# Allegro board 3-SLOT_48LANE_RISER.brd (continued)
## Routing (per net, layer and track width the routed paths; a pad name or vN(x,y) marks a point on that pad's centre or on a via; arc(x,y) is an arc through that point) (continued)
85OHM_BOT_10INCH_DN: length 254
  BOTTOM w0.135: U43.1 -14.63,9.78 -14.63,12.53 -14.17,13.19 -13.48,13.31 -10.22,12.73 -9.99,12.89 -9.99,12.89 -9.88,12.97 -9.73,13.85 -9.99,14.22 -17.14,15.49 -17.32,15.74 -17.23,16.22 -17.01,16.37 -8.76,14.92 -8.4,15.16 -8.25,16.05 -8.49,16.4 -17.42,17.98 -17.54,18.14 -17.43,18.73 -17.26,18.86 -8.77,17.36 -8.39,17.63 -8.25,18.43 -8.54,18.85 -17.24,20.39 -17.38,20.58 -17.28,21.15 -17.1,21.27 -8.71,19.79 -8.29,20.09 -8.17,20.78 -8.42,21.29 -17.55,22.9 -17.71,23.13 -17.62,23.66 -17.45,23.77 -8.44,22.19 -8.04,22.46 -7.89,23.3 -8.15,23.67 -17.49,25.31 -17.64,25.51 -17.56,26.04 -17.37,26.2 -8.54,24.65 -8.12,24.94 -7.98,25.76 -8.23,26.12 -17.39,27.75 -17.52,27.94 -17.42,28.51 -17.26,28.63 -8.25,27.04 -7.87,27.3 -7.73,28.12 -8.01,28.52 -17.56,30.21 -17.67,30.38 -17.57,30.96 -17.39,31.09 -8.22,29.47 -7.82,29.75 -7.68,30.55 -7.97,30.96 -17.49,32.64 -17.6,32.79 -17.49,33.4 -17.32,33.52 -8.18,31.91 -7.79,32.18 -7.65,33 -7.93,33.39 -17.43,35.07 -17.58,35.28 -17.48,35.86 -17.33,35.96 -8.27,34.36 -7.79,34.69 -7.67,35.43 -7.96,35.84 -17.43,37.51 -17.55,37.69 -17.45,38.27 -17.26,38.39 -7.96,36.75 -7.53,37.05 -7.41,37.76 -7.75,38.25 -17.58,39.98 -17.71,40.17 -17.62,40.7 -17.39,40.86 -7.78,39.16 -7.36,39.46 -7.22,40.22 -7.52,40.65 -14.84,41.94 -14.95,42.09 -14.75,43.2 -14.75,45.47 U45.2
85OHM_BOT_10INCH_DP: length 254
  BOTTOM w0.135: U45.1 -15.06,45.46 -15.06,43.23 -15.27,42.02 -15.02,41.66 -7.7,40.37 -7.55,40.15 -7.64,39.63 -7.85,39.48 -17.46,41.18 -17.9,40.88 -18.03,40.1 -17.76,39.7 -7.93,37.97 -7.73,37.69 -7.81,37.23 -8.03,37.07 -17.33,38.71 -17.72,38.45 -17.88,37.62 -17.61,37.23 -8.13,35.56 -7.99,35.35 -8.07,34.87 -8.34,34.69 -17.4,36.28 -17.75,36.04 -17.9,35.21 -17.61,34.79 -8.1,33.12 -7.97,32.93 -8.07,32.36 -8.25,32.23 -17.39,33.84 -17.77,33.58 -17.92,32.72 -17.67,32.36 -8.15,30.68 -8.01,30.48 -8.1,29.93 -8.3,29.8 -17.46,31.41 -17.85,31.14 -18,30.3 -17.73,29.93 -8.18,28.25 -8.05,28.05 -8.15,27.48 -8.32,27.36 -17.33,28.95 -17.7,28.69 -17.72,28.57 -17.84,27.87 -17.56,27.48 -8.41,25.84 -8.3,25.69 -8.4,25.12 -8.61,24.97 -17.45,26.53 -17.85,26.21 -17.95,25.43 -17.67,25.03 -8.32,23.39 -8.21,23.23 -8.32,22.64 -8.51,22.51 -17.52,24.1 -17.9,23.84 -17.92,23.71 -18.03,23.05 -17.73,22.62 -8.63,21.02 -8.48,20.73 -8.57,20.26 -8.78,20.12 -17.17,21.6 -17.56,21.33 -17.7,20.51 -17.42,20.11 -8.72,18.57 -8.57,18.36 -8.67,17.8 -8.84,17.68 -17.33,19.18 -17.71,18.91 -17.86,18.07 -17.6,17.7 -8.67,16.12 -8.57,15.98 -8.68,15.34 -8.83,15.24 -17.08,16.7 -17.51,16.4 -17.64,15.67 -17.32,15.21 -10.17,13.95 -10.05,13.78 -10.16,13.14 -10.29,13.06 -13.48,13.62 -14.35,13.46 -14.94,12.62 -14.94,9.77 U43.2
85OHM_L2_5INCH_DN: length 127
  TOP w0.135: v2(-7.16,258.4) -7.39,258.17 -7.39,257.76 U29.2 ; v2(-7.16,278.38) -7.39,278.61 -7.39,279.02 U25.1
  IN2 w0.145: v2(-7.16,278.38) -7.4,278.14 -7.4,276.39 -6.9,275.67 -5.04,275.34 -4.69,274.85 -4.8,274.25 -5.3,273.9 -12.66,275.2 -12.82,275.08 -12.93,274.47 -12.81,274.31 -5.45,273.01 -5.1,272.51 -5.21,271.91 -5.71,271.56 -13.2,272.88 -13.37,272.77 -13.48,272.16 -13.36,271.99 -5.87,270.67 -5.52,270.17 -5.62,269.57 -6.12,269.22 -13.71,270.56 -13.88,270.45 -13.99,269.84 -13.87,269.67 -6.28,268.33 -5.93,267.83 -6.04,267.23 -6.53,266.89 -14.58,268.31 -14.75,268.19 -14.85,267.58 -14.74,267.41 -6.69,265.99 -6.34,265.5 -6.45,264.9 -6.95,264.55 -16.13,266.17 -16.44,265.95 -16.51,265.58 -16.29,265.28 -7.1,263.66 -6.75,263.16 -6.86,262.56 -7.36,262.21 -16.55,263.83 -16.85,263.62 -16.92,263.25 -16.7,262.94 -7.52,261.32 -7.17,260.82 -7.4,259.49 -7.4,258.64 v2(-7.16,258.4)
85OHM_L2_5INCH_DP: length 127
  TOP w0.135: U25.2 -7.69,279.02 -7.69,278.62 v2(-7.92,278.38) ; U29.1 -7.69,257.77 -7.69,258.17 v2(-7.92,258.4)
  IN2 w0.145: v2(-7.92,258.4) -7.68,258.64 -7.68,259.51 -7.46,260.75 -7.68,261.06 -16.87,262.68 -17.21,263.18 -17.11,263.78 -16.61,264.13 -7.42,262.51 -7.12,262.72 -7.05,263.09 -7.27,263.4 -16.45,265.02 -16.8,265.52 -16.7,266.12 -16.2,266.46 -7.01,264.84 -6.7,265.06 -6.64,265.43 -6.85,265.74 -14.9,267.16 -15.15,267.51 -15,268.35 -14.64,268.6 -6.6,267.18 -6.29,267.4 -6.23,267.77 -6.44,268.08 -14.03,269.41 -14.28,269.77 -14.13,270.61 -13.78,270.86 -6.19,269.52 -5.88,269.73 -5.81,270.11 -6.03,270.41 -13.53,271.74 -13.78,272.09 -13.63,272.93 -13.27,273.18 -5.77,271.86 -5.47,272.07 -5.4,272.44 -5.62,272.75 -12.98,274.05 -13.23,274.41 -13.08,275.24 -12.72,275.49 -5.36,274.2 -5.05,274.41 -4.99,274.78 -5.2,275.09 -7.04,275.41 -7.06,275.42 -7.68,276.3 -7.68,278.14 v2(-7.92,278.38)
85OHM_L2_10INCH_DN: length 254
  TOP w0.135: U37.2 -7.94,107.06 -7.94,106.66 v2(-8.18,106.43) ; v2(-8.18,72.01) -7.95,71.78 -7.95,71.37 U33.1
  IN2 w0.145: v2(-8.18,106.43) -7.94,106.18 -7.94,104.78 -7.79,103.98 -6.64,102.33 -6.77,101.6 -6.93,101.48 -12.68,102.49 -13.16,102.15 -13.27,101.53 -12.94,101.05 -4.14,99.5 -4.02,99.33 -4.13,98.72 -4.3,98.6 -13.09,100.15 -13.59,99.8 -13.7,99.21 -13.35,98.71 -4.56,97.16 -4.45,96.99 -4.55,96.38 -4.72,96.27 -13.51,97.82 -14,97.47 -14.11,96.87 -13.76,96.37 -4.86,94.8 -4.75,94.64 -4.85,94.03 -5.02,93.91 -13.92,95.48 -14.41,95.13 -14.52,94.53 -14.17,94.03 -5.17,92.45 -5.06,92.28 -5.16,91.67 -5.33,91.55 -14.33,93.14 -14.83,92.79 -14.93,92.19 -14.58,91.7 -4.58,89.93 -4.46,89.76 -4.57,89.16 -4.73,89.04 -14.74,90.8 -15.24,90.45 -15.34,89.86 -15,89.36 -4.97,87.59 -4.82,87.38 -4.92,86.81 -5.09,86.69 -15.15,88.46 -15.65,88.12 -15.76,87.52 -15.41,87.02 -5.29,85.24 -5.12,85 -5.22,84.45 -5.39,84.33 -15.57,86.13 -16.06,85.78 -16.17,85.18 -15.82,84.68 -5.6,82.88 -5.44,82.65 -5.53,82.17 -5.78,81.99 -15.98,83.79 -16.48,83.44 -16.58,82.84 -16.23,82.34 -5.8,80.51 -5.65,80.29 -5.75,79.74 -5.94,79.61 -16.39,81.45 -16.89,81.1 -16.99,80.5 -16.65,80.01 -6.44,78.21 -6.27,77.96 -6.35,77.52 -6.63,77.32 -16.8,79.11 -17.3,78.76 -17.41,78.17 -17.06,77.67 -7.69,76.02 -7.48,75.71 -7.94,73.12 -7.94,72.25 v2(-8.18,72.01)
85OHM_L2_10INCH_DP: length 254
  TOP w0.135: v2(-7.42,72.01) -7.65,71.78 -7.65,71.37 U33.2 ; U37.1 -7.64,107.06 -7.64,106.65 v2(-7.42,106.43)
  IN2 w0.145: v2(-7.42,106.43) -7.66,106.18 -7.66,104.81 -7.53,104.09 -6.34,102.39 -6.51,101.43 -6.87,101.18 -12.62,102.2 -12.91,101.99 -12.98,101.6 -12.77,101.3 -3.98,99.75 -3.79,99.49 -3.73,99.39 -3.88,98.56 -4.23,98.31 -13.03,99.86 -13.34,99.64 -13.4,99.27 -13.18,98.96 -4.4,97.42 -4.15,97.06 -4.3,96.22 -4.66,95.97 -13.44,97.52 -13.75,97.3 -13.81,96.93 -13.6,96.63 -4.7,95.06 -4.45,94.7 -4.6,93.86 -4.96,93.61 -13.85,95.18 -14.16,94.97 -14.23,94.6 -14.01,94.29 -5.01,92.7 -4.76,92.35 -4.91,91.51 -5.27,91.26 -14.26,92.84 -14.57,92.63 -14.64,92.26 -14.42,91.95 -4.42,90.19 -4.29,90 -4.16,89.82 -4.31,88.99 -4.67,88.74 -14.68,90.51 -14.98,90.29 -15.05,89.92 -14.83,89.61 -4.81,87.85 -4.53,87.45 -4.67,86.64 -5.03,86.39 -15.09,88.17 -15.4,87.95 -15.46,87.58 -15.25,87.28 -5.13,85.49 -4.83,85.06 -4.97,84.29 -5.32,84.04 -15.5,85.83 -15.81,85.62 -15.87,85.25 -15.66,84.94 -5.44,83.14 -5.15,82.72 -5.27,82 -5.71,81.69 -15.91,83.49 -16.22,83.28 -16.29,82.91 -16.07,82.6 -5.64,80.76 -5.36,80.36 -5.49,79.58 -5.88,79.31 -16.33,81.16 -16.63,80.94 -16.7,80.57 -16.48,80.26 -6.28,78.46 -5.97,78.03 -6.09,77.35 -6.56,77.02 -16.74,78.82 -17.05,78.6 -17.11,78.23 -16.9,77.92 -7.53,76.27 -7.18,75.78 -7.66,73.1 -7.66,72.44 -7.49,72.04 v2(-7.42,72.01)
85OHM_TOP_5INCH_DN: length 127
  TOP w0.135: U26.2 -14.93,340.62 -14.93,338.38 -15.14,337.17 -14.89,336.81 -7.57,335.52 -7.42,335.3 -7.51,334.78 -7.72,334.63 -17.34,336.33 -17.77,336.02 -17.91,335.24 -17.77,335.05 -17.63,334.85 -7.63,333.09 -7.4,332.76 -7.48,332.3 -7.66,332.18 -17.21,333.86 -17.6,333.6 -17.75,332.76 -17.48,332.38 -7.91,330.69 -7.7,330.39 -7.79,329.89 -7.93,329.79 -17.05,331.39 -17.43,331.13 -17.58,330.31 -17.29,329.91 -8.27,328.32 -8.09,328.05 -8.18,327.52 -8.33,327.41 -17.2,328.98 -17.59,328.71 -17.74,327.87 -17.47,327.5 -8.54,325.92 -8.44,325.77 -8.55,325.14 -8.7,325.04 -16.96,326.49 -17.38,326.2 -17.51,325.47 -17.19,325.01 -10.04,323.74 -9.92,323.57 -10.04,322.94 -10.16,322.85 -13.35,323.42 -14.22,323.26 -14.81,322.42 -14.81,319.58 U5.1
85OHM_TOP_5INCH_DP: length 127
  TOP w0.135: U5.2 -14.51,319.58 -14.51,322.33 -14.04,322.98 -13.35,323.11 -10.09,322.53 -9.86,322.69 -9.76,322.76 -9.6,323.65 -9.87,324.02 -17.01,325.28 -17.19,325.54 -17.1,326.02 -16.89,326.17 -8.63,324.72 -8.27,324.96 -8.12,325.85 -8.37,326.2 -17.3,327.78 -17.41,327.94 -17.31,328.53 -17.13,328.66 -8.26,327.09 -7.9,327.34 -7.77,328.13 -8.09,328.59 -17.12,330.19 -17.25,330.38 -17.2,330.66 -17.15,330.95 -16.98,331.07 -7.86,329.46 -7.69,329.59 -7.68,329.59 -7.51,329.71 -7.38,330.46 -7.56,330.72 -7.74,330.97 -17.31,332.66 -17.43,332.83 -17.37,333.13 -17.32,333.42 -17.14,333.54 -7.58,331.86 -7.2,332.12 -7.08,332.83 -7.45,333.36 -17.45,335.13 -17.59,335.32 -17.49,335.85 -17.27,336 -7.65,334.31 -7.23,334.61 -7.1,335.37 -7.39,335.79 -14.71,337.09 -14.82,337.24 -14.63,338.35 -14.63,340.62 U26.1
85OHM_TOP_10INCH_DN: length 254
  TOP w0.135: U34.2 -14.93,164.85 -14.93,162.61 -15.14,161.4 -14.89,161.04 -7.57,159.75 -7.42,159.53 -7.51,159.01 -7.72,158.86 -17.34,160.56 -17.77,160.26 -17.91,159.48 -17.63,159.08 -7.8,157.35 -7.6,157.07 -7.68,156.61 -7.9,156.45 -17.21,158.09 -17.6,157.83 -17.75,157 -17.48,156.61 -8.01,154.94 -7.86,154.73 -7.95,154.25 -8.21,154.07 -17.27,155.66 -17.63,155.42 -17.77,154.59 -17.48,154.17 -7.98,152.5 -7.84,152.31 -7.94,151.74 -8.12,151.61 -17.27,153.22 -17.64,152.96 -17.79,152.1 -17.54,151.74 -8.02,150.06 -7.88,149.86 -7.98,149.31 -8.17,149.18 -17.33,150.79 -17.72,150.52 -17.87,149.68 -17.61,149.31 -8.06,147.63 -7.92,147.43 -8.02,146.86 -8.2,146.74 -17.2,148.33 -17.57,148.07 -17.59,147.95 -17.71,147.25 -17.44,146.86 -8.28,145.22 -8.17,145.07 -8.27,144.5 -8.49,144.35 -17.32,145.91 -17.72,145.59 -17.83,144.81 -17.54,144.41 -8.2,142.77 -8.09,142.61 -8.19,142.02 -8.38,141.89 -17.39,143.48 -17.77,143.22 -17.79,143.09 -17.91,142.43 -17.6,142 -8.5,140.4 -8.36,140.11 -8.44,139.64 -8.65,139.5 -17.05,140.98 -17.43,140.71 -17.58,139.89 -17.29,139.49 -8.59,137.95 -8.44,137.74 -8.54,137.18 -8.71,137.06 -17.2,138.56 -17.59,138.29 -17.74,137.45 -17.47,137.08 -8.54,135.5 -8.44,135.36 -8.55,134.72 -8.7,134.62 -16.96,136.08 -17.38,135.78 -17.51,135.05 -17.19,134.59 -10.04,133.33 -9.92,133.16 -10.04,132.52 -10.16,132.44 -13.35,133 -14.22,132.84 -14.81,132 -14.81,129.16 U30.1
85OHM_TOP_10INCH_DP: length 254
  TOP w0.135: U30.2 -14.51,129.16 -14.51,131.91 -14.04,132.57 -13.35,132.69 -10.09,132.11 -9.86,132.27 -9.86,132.27 -9.76,132.35 -9.6,133.23 -9.87,133.6 -17.01,134.87 -17.19,135.12 -17.1,135.6 -16.89,135.75 -8.63,134.3 -8.27,134.54 -8.12,135.43 -8.37,135.78 -17.3,137.36 -17.41,137.52 -17.31,138.11 -17.13,138.24 -8.64,136.74 -8.26,137.01 -8.12,137.81 -8.42,138.23 -17.12,139.77 -17.25,139.96 -17.15,140.53 -16.98,140.65 -8.58,139.17 -8.16,139.47 -8.04,140.16 -8.29,140.67 -17.43,142.28 -17.58,142.51 -17.49,143.04 -17.32,143.15 -8.31,141.57 -7.91,141.84 -7.76,142.68 -8.02,143.05 -17.37,144.69 -17.51,144.89 -17.44,145.42 -17.24,145.58 -8.42,144.03 -7.99,144.32 -7.85,145.14 -8.11,145.5 -17.26,147.13 -17.39,147.32 -17.29,147.89 -17.13,148.01 -8.13,146.42 -7.75,146.68 -7.6,147.5 -7.88,147.9 -17.43,149.59 -17.55,149.76 -17.45,150.34 -17.26,150.47 -8.1,148.85 -7.7,149.13 -7.56,149.93 -7.84,150.34 -17.37,152.02 -17.47,152.17 -17.36,152.78 -17.19,152.9 -8.05,151.29 -7.66,151.56 -7.52,152.38 -7.8,152.77 -17.3,154.45 -17.45,154.66 -17.35,155.24 -17.2,155.34 -8.14,153.74 -7.67,154.07 -7.54,154.81 -7.83,155.22 -17.31,156.89 -17.43,157.07 -17.32,157.65 -17.14,157.77 -7.83,156.13 -7.41,156.43 -7.28,157.14 -7.62,157.63 -17.45,159.36 -17.59,159.55 -17.49,160.08 -17.27,160.24 -7.65,158.54 -7.23,158.84 -7.1,159.6 -7.39,160.03 -14.71,161.32 -14.82,161.47 -14.63,162.58 -14.63,164.85 U34.1
AT24C64_A0: length 4.7
  TOP w0.114: U7.1 315.16,41.63 315.65,42.11 315.65,43.61 R282.1 v2(315.16,44.78) R281.2
AT24C64_A1: length 4.7
  TOP w0.114: 313.89,41.12 313.89,41.88 314.34,42.32 314.34,43.64 R284.1 v2(313.89,44.78) R283.2
AT24C64_A2: length 4.7
  TOP w0.114: U7.3 312.62,41.78 313.13,42.29 313.13,43.58 R286.1 v2(312.62,44.78) R285.2
CLK_100M_CPU1_PE_FG_DN: length 76.6
  TOP w0.135: v2(280.62,9.91) 280.93,9.6 280.93,6.78 281.17,6.53 281.17,6.15 280.83,5.8 J5.A14 ; 301.31,56.32 U9.7 301.31,55.38 302.93,53.77 302.93,48.99 v2(303.15,48.77)
  IN2 w0.145: v2(280.62,9.91) 280.93,9.6 280.93,9.22 281.26,8.89 282.27,8.89 283.39,10.01 298.38,10.01 302.59,14.23 302.59,18.62 304.65,20.67 304.65,29.26 304.42,29.49 304.42,30.68 304.12,30.99 304.12,32.18 304.65,32.72 304.65,38.38 303.4,39.62 303.4,45.4 302.87,45.94 302.87,48.49 v2(303.15,48.77)
CLK_100M_CPU1_PE_FG_DP: length 76.6
  TOP w0.135: 300.91,56.32 U9.6 300.91,55.73 301.01,55.64 301.01,55.26 302.62,53.64 302.62,49.05 v2(302.34,48.77) ; v2(281.51,9.91) 281.23,9.63 281.23,6.91 281.48,6.66 281.48,6.15 281.83,5.8 J5.A13
  IN2 w0.145: v2(281.51,9.91) 281.21,9.6 281.21,9.34 281.37,9.17 282.16,9.17 283.27,10.29 298.26,10.29 298.76,10.79 298.76,10.95 299.2,11.39 299.36,11.39 300.72,12.75 300.72,12.91 301.17,13.36 301.33,13.36 302.32,14.34 302.32,18.73 304.37,20.79 304.37,21.59 304.28,21.68 304.28,22.45 304.37,22.54 304.37,23.44 304.24,23.57 304.24,24.2 304.37,24.32 304.37,24.9 304.24,25.03 304.24,25.66 304.37,25.79 304.37,26.36 304.24,26.49 304.24,27.12 304.37,27.25 304.37,29.14 304.14,29.37 304.14,30.57 303.84,30.87 303.84,32.3 304.37,32.83 304.37,34.3 304.26,34.41 304.26,35.04 304.37,35.15 304.37,36.01 304.26,36.12 304.26,36.75 304.37,36.87 304.37,38.26 303.13,39.51 303.13,45.29 302.59,45.82 302.59,46.96 302.46,47.09 302.46,47.72 302.59,47.84 302.59,48.51 v2(302.34,48.77)
CLK_100M_PEX8796_DN: length 3.8
  TOP w0.135: 301.31,61.07 U9.24 301.31,61.59 301.36,61.64 301.36,62.39 301.95,62.98 301.95,64.12 R127.1
CLK_100M_PEX8796_DP: length 3.8
  TOP w0.135: 301.71,61.07 U9.23 301.71,61.58 301.66,61.63 301.66,62.26 302.26,62.86 302.26,64.17 R126.1
CLK_100M_PEX8796_R_DN: length 302.9
  TOP w0.135: v2(276.2,30.3) 275.95,30.56 275.95,33.81 276.96,34.82 276.96,38.13 277.95,39.12 277.95,45.21 278.78,46.04 278.88,46.04 278.88,46.03 278.98,46.03 279.29,46.35 279.29,46.45 279.29,46.45 279.29,46.55 281.17,48.43 281.34,48.43 281.76,48.86 281.76,49.02 283.57,50.83 283.77,50.83 284.08,51.14 284.08,51.34 291.79,59.05 291.89,59.05 291.89,59.05 291.99,59.05 292.3,59.36 292.3,59.46 292.3,59.46 292.3,59.56 294.31,61.57 294.54,61.57 294.73,61.76 294.73,61.99 294.93,62.19 295.16,62.19 295.35,62.38 295.35,62.61 295.55,62.81 295.78,62.81 295.98,63.01 295.98,63.23 297.18,64.44 v6(297.18,65.76) 297.18,67.49 297.95,68.26 301.39,68.26 301.93,67.72 301.93,65.66 R127.2
  IN2 w0.145: v3(56.85,67.16) 56.85,67.28 56.71,67.42 56.49,67.42 56.24,67.17 56.24,61.84 65.51,52.58 73.27,52.58 74.62,51.23 74.76,51.23 75.24,50.75 75.24,50.61 76.37,49.48 81.33,49.48 81.46,49.61 82.09,49.61 82.21,49.48 82.79,49.48 82.91,49.61 83.54,49.61 83.67,49.48 93.48,49.48 101.41,57.41 154.68,57.41 181.15,30.94 258.64,30.94 258.77,31.06 259.4,31.06 259.53,30.94 260.11,30.94 260.23,31.06 260.86,31.06 260.99,30.94 273.08,30.94 273.99,31.85 275.4,31.85 275.92,31.33 275.92,30.58 v2(276.2,30.3)
  BOTTOM w0.135: U1.W2 57.25,67.56 v3(56.85,67.16)
CLK_100M_PEX8796_R_DP: length 303
  TOP w0.135: R126.2 302.23,65.66 302.23,67.85 301.51,68.57 297.83,68.57 296.88,67.62 v6(296.88,67.34) 296.88,64.57 277.65,45.34 277.65,39.24 276.66,38.25 276.66,34.95 275.64,33.93 275.64,30.56 v2(275.39,30.3)
  IN2 w0.145: v3(56.85,67.96) 56.85,67.82 56.73,67.7 56.38,67.7 55.96,67.29 55.96,61.73 65.39,52.3 73.15,52.3 76.25,49.2 93.6,49.2 101.52,57.13 154.57,57.13 181.04,30.66 273.19,30.66 274.11,31.57 275.29,31.57 275.64,31.22 275.64,30.56 v2(275.39,30.3)
  BOTTOM w0.135: U1.W3 57.25,68.36 v3(56.85,67.96)
CLK_100M_SLOT1_DN: length 3.8
  TOP w0.135: 303.09,58.5 U9.15 303.61,58.5 303.65,58.45 304.49,58.45 305.08,57.86 306.13,57.86 R340.1
CLK_100M_SLOT1_DP: length 3.8
  TOP w0.135: 303.09,58.1 U9.14 303.6,58.1 303.65,58.15 304.36,58.15 304.96,57.55 306.18,57.55 R143.1
CLK_100M_SLOT1_R_DN: length 79
  TOP w0.135: v2(309.2,51.21) 308.97,51.43 308.97,57.28 308.37,57.88 307.67,57.88 R340.2
  IN2 w0.145: v2(309.2,51.21) 308.94,50.95 308.94,50.22 308.33,49.61 306.45,49.61 305.89,50.16 301.72,50.16 301.04,49.49 301.04,46.3 301.96,45.39 301.96,42.02 301.7,41.77 301.7,40.17 301.96,39.92 301.96,35.99 301.27,35.31 301.27,32.74 302.03,31.98 302.03,19.97 301.43,19.37 301.43,15.08 297.15,10.79 282.51,10.79 281.74,11.57 281.74,13.49 281.69,13.54 281.39,13.74 281.2,13.68 J1.A14
CLK_100M_SLOT1_R_DP: length 79
  TOP w0.135: R143.2 307.67,57.58 308.24,57.58 308.66,57.16 308.66,55.75 308.54,55.62 308.54,54.73 308.66,54.6 308.66,51.49 v2(308.38,51.21)
  IN2 w0.145: v2(308.38,51.21) 308.66,50.93 308.66,50.33 308.22,49.89 306.57,49.89 306.01,50.44 304.6,50.44 304.48,50.56 303.85,50.56 303.74,50.44 303.14,50.44 303.02,50.56 302.39,50.56 302.28,50.44 301.6,50.44 300.76,49.61 300.76,48.25 300.65,48.13 300.65,47.5 300.76,47.39 300.76,46.19 301.68,45.27 301.68,44.18 301.56,44.07 301.56,43.44 301.68,43.33 301.68,42.14 301.42,41.88 301.42,40.06 301.68,39.8 301.68,37.73 301.58,37.63 301.58,36.94 301.68,36.84 301.68,36.11 300.99,35.42 300.99,32.62 301.75,31.86 301.75,26.66 301.63,26.53 301.63,25.85 301.75,25.72 301.75,25.14 301.63,25.02 301.63,24.34 301.75,24.21 301.75,23.1 301.64,22.98 301.64,22.36 301.75,22.24 301.75,21.39 301.64,21.27 301.64,20.64 301.75,20.53 301.75,20.09 301.15,19.49 301.15,15.2 300.16,14.2 299.99,14.2 299.55,13.76 299.55,13.6 297.03,11.07 282.63,11.07 282.02,11.68 282.02,13.61 281.74,13.88 281.52,13.99 281.52,14 281.46,14.19 J1.A13
CLK_100M_SLOT2_DN: length 4
  TOP w0.135: 303.09,59.7 U9.18 303.55,59.7 303.6,59.65 304.06,59.65 304.47,60.07 305.06,60.07 305.67,60.68 306.16,60.68 R125.1
CLK_100M_SLOT2_DP: length 4
  TOP w0.135: 303.09,59.3 U9.17 303.58,59.3 303.63,59.35 304.18,59.35 304.6,59.76 305.19,59.76 305.79,60.37 306.16,60.37 R124.1
CLK_100M_SLOT2_R_DN: length 62.2
  TOP w0.135: R125.2 307.67,60.68 308.74,60.68 310.77,58.65 310.77,54.1 v2(311,53.87)
  BOTTOM w0.135: v2(311,53.87) 310.8,53.67 310.8,35.51 309.55,34.26 299.7,34.26 296.42,30.99 283.03,30.99 281.64,32.39 281.64,33.86 281.51,33.99 281.38,34.06 281.2,34 J2.A14
CLK_100M_SLOT2_R_DP: length 62.1
  TOP w0.135: v2(310.19,53.87) 310.47,54.15 310.47,58.53 308.62,60.37 307.67,60.37 R124.2
  BOTTOM w0.135: v2(310.19,53.87) 310.49,53.57 310.49,49.43 310.29,49.23 310.29,48.79 310.49,48.59 310.49,35.64 309.43,34.57 301.84,34.57 301.69,34.72 301.2,34.72 301.04,34.57 299.57,34.57 298.61,33.61 298.51,33.61 298.41,33.61 298.09,33.3 298.09,33.2 298.09,33.09 296.29,31.29 295.42,31.29 295.24,31.47 294.8,31.47 294.62,31.29 290.45,31.29 290.27,31.47 289.83,31.47 289.65,31.29 285.95,31.29 285.77,31.47 285.33,31.47 285.15,31.29 283.16,31.29 282.73,31.73 282.73,31.94 282.44,32.23 282.23,32.23 281.94,32.51 281.94,33.99 281.69,34.25 281.52,34.33 281.46,34.51 J2.A13
CLK_100M_SLOT3_DN: length 4
  TOP w0.135: R123.1 299.13,64.14 299.13,63.08 300.16,62.06 300.16,61.58 300.11,61.54 U9.27 300.11,61.07
CLK_100M_SLOT3_DP: length 4
  TOP w0.135: 300.51,61.07 U9.26 300.51,61.57 300.46,61.61 300.46,62.18 299.44,63.21 299.44,64.14 R122.1
CLK_100M_SLOT3_R_DN: length 27.4
  TOP w0.135: R123.2 299.13,65.66 299.13,66.58 v2(298.86,66.85)
  BOTTOM w0.135: v2(298.86,66.85) 299.09,67.08 299.09,67.41 298.81,67.69 297.18,67.69 296.65,67.16 293.29,67.16 293.12,66.98 292.68,66.98 292.5,67.16 289.44,67.16 289.26,66.98 288.82,66.98 288.64,67.16 284.71,67.16 282.64,69.23 282.64,72.02 281.64,73.02 281.64,74.5 281.51,74.63 281.38,74.7 281.2,74.64 J3.A14
CLK_100M_SLOT3_R_DP: length 27.5
  TOP w0.135: R122.2 299.44,65.66 299.44,66.62 v2(299.67,66.86)
  BOTTOM w0.135: J3.A13 281.46,75.15 281.52,74.97 281.69,74.89 281.94,74.63 281.94,73.15 282.95,72.14 282.95,69.35 284.84,67.46 296.52,67.46 297.06,68 298.93,68 299.39,67.54 299.39,67.14 v2(299.67,66.86)
CLK_BUF_CKPWRGD: length 6.8
  TOP w0.114: Q4.D 299.8,51.02 R4.2 299.31,55.26 299.71,55.66 U9.3 299.71,56.32
CLK_BUF_HIBW_BYPM_LOBW_N: length 4
  TOP w0.178: 299.31,56.32 U9.2 299.31,55.67 298.79,55.14 298.79,54.94
  TOP w0.254: R1.2 R2.1 298.79,53.94 298.79,54.94
CPLD_PWRBRK_BUF_N: length 75.9
  TOP w0.114: v2(286.67,58.17) 286.7,58.13 R310.1 285.39,57.4 U8.4 ; U47.2 276.68,29.31 277.47,30.1 277.47,31.29 278.46,32.28 279.55,32.28 279.86,32.59 279.86,34.09 280.7,34.92 280.7,36.32 281.08,36.7 281.94,36.7 284.74,39.5 v2(284.74,41.1) ; U19.2 v2(283.54,85.72) ; v2(283.54,45.34) 283.41,45.21 U20.2
  IN2 w0.147: v2(284.74,41.1) 284.71,41.1 283.05,42.76 283.05,44.84 v2(283.54,45.34) 283.54,47.02 287.17,50.65 287.17,56.92 286.67,57.43 v2(286.67,58.17) 285.73,58.17 285.1,58.79 285.1,61.81 280.9,66.01 280.9,69.34 286.84,75.29 286.84,78.77 282.88,82.73 282.88,85.52 283.08,85.72 v2(283.54,85.72)
CPLD_PWRBRK_N: length 80.8
  TOP w0.114: U8.2 283.54,58.17 283.8,57.91 283.8,56.41 R309.2 283.78,55.9 284.05,55.63 286.08,55.63 v2(286.59,56.13)
  IN2 w0.147: v2(266.4,25.02) 267.92,26.54 276.28,26.54 278.36,28.63 281.04,28.63 284.01,31.6 286.31,31.6 287.73,33.02 287.73,34.19 286.69,35.23 286.69,38.23 282.53,42.39 282.53,46.74 286.59,50.8 v2(286.59,56.13)
  BOTTOM w0.114: J5.B30 264.83,5.58 263.7,6.71 263.7,11.86 263.98,12.14 263.98,13.79 264.72,14.53 264.72,17.86 265.86,19 265.86,20.27 266.52,20.93 266.52,24.89 v2(266.4,25.02)
CPLD_SLOT1_PWRBRK_N: length 3.7
  TOP w0.114: R40.1 274.76,25.15 R39.1 R164.2 v2(275.92,25.91) 276.03,26.02 U47.4
CPLD_SLOT1_PWRBRK_R1_N: length 10.8
  TOP w0.114: J1.B12 282.83,20.83 279.96,23.7 275.7,23.7 R39.2
CPLD_SLOT1_PWRBRK_R2_N: length 11.6
  TOP w0.114: J1.B30 266.96,21.56 270.96,21.56 272.35,22.95 272.35,24.62 272.87,25.15 R40.2
CPLD_SLOT2_PWRBRK_N: length 4.1
  TOP w0.114: R221.1 R216.1 R154.2 285.14,43.45 285.35,43.66 v2(285.35,44.07) 285.35,44.37 285.16,44.56 U20.4
CPLD_SLOT2_PWRBRK_R1_N: length 3.3
  TOP w0.114: J2.B12 283.8,40.72 R216.2
CPLD_SLOT2_PWRBRK_R2_N: length 19.2
  TOP w0.114: R221.2 v2(278.74,42.65)
  IN1 w0.147: v2(278.74,42.65) 267.73,42.65 J2.B30
CPLD_SLOT3_PWRBRK_N: length 3.8
  TOP w0.114: U19.4 284.03,85.08 283.8,84.84 v2(283.8,84.71) R214.1 ; R155.2 R214.1 ; R214.1 R215.1
CPLD_SLOT3_PWRBRK_R1_N: length 3.2
  TOP w0.114: R214.2 283.8,81.36 J3.B12
CPLD_SLOT3_PWRBRK_R2_N: length 19.1
  TOP w0.114: J3.B30 267.6,83.17 R215.2
DC_PEX8747_AA18: length 0.6
  BOTTOM w0.114: U1.AA18 v3(55.25,80.77)
DC_PEX8747_AA21: length 0.6
  BOTTOM w0.114: U1.AA21 v3(56.05,83.17)
DC_PEX8747_B9: length 0.6
  BOTTOM w0.114: U1.B9 v3(70.45,72.76)
DC_PEX8747_F13: length 0.6
  BOTTOM w0.114: U1.F13 v3(68.05,76.77)
DC_PEX8747_F20: length 0.6
  BOTTOM w0.114: U1.F20 v3(68.05,82.37)
DC_PEX8747_F21: length 0.6
  BOTTOM w0.114: U1.F21 67.65,82.77 v3(67.25,83.17)
DC_PEX8747_N22: length 0.6
  BOTTOM w0.114: U1.N22 62.05,83.57 v3(61.65,83.97)
DC_PEX8747_Y16: length 0.6
  BOTTOM w0.114: U1.Y16 v3(56.05,79.17)
DC_PEX8747_Y20: length 0.6
  BOTTOM w0.114: U1.Y20 v3(56.05,82.37)
EMC1413_ADDR: length 4.9
  TOP w0.114: U10.7 184.33,78 v2(185.98,76.35) 186.49,75.84 187.61,75.84 R150.2
EMC1413_ALERT_N: length 4.6
  TOP w0.114: U10.8 184.83,78.5 v2(185.35,77.98) 186.14,77.19 187.41,77.19 R151.2
I2C_ADDR0: length 7.7
  TOP w0.102: v3(68.05,69.56) 67.67,69.18 67.13,69.18 66.87,68.92 66.87,68.59 66.5,68.22 66.5,65.66
  TOP w0.114: R94.2 R108.1 66.37,64.96 66.5,65.09 66.5,65.66
  BOTTOM w0.114: U1.F5 v3(68.05,69.56)
I2C_MUX_ADD_A0: length 6.7
  TOP w0.114: U2.1 308.04,41.16 308.54,41.66 v2(309.32,41.66) 309.45,41.78 309.45,43.69 309.72,43.96 R84.1 R83.2
I2C_MUX_ADD_A1: length 5.9
  TOP w0.114: R81.2 v2(308.81,44.73) R82.1 308.23,43.38 308.23,41.88 307.39,41.04 U2.2
I2C_MUX_ADD_A2: length 5.7
  TOP w0.114: R79.2 R80.1 306.45,31.07 306.45,31.85 v2(306.2,32.11) 306.09,32.21 U2.21
I2C_MUX_RST_N: length 3.4
  TOP w0.114: R78.2 307.67,42.62 v2(307.37,42.32) 307.34,42.32 306.74,41.72 U2.3
I2C_PCA9548_SC1_SLOT3_R_SCL: length 3.2
  TOP w0.114: U2.7 304.14,41.53 v2(304.1,41.57) 303.61,42.06 R22.1
I2C_PCA9548_SC1_SLOT3_SCL: length 36.4
  TOP w0.114: R22.2 304.24,44.6 v2(304.24,44.7) R98.2 ; v2(292.22,65.11) Q15.D 291.78,67.24 R226.1
  BOTTOM w0.114: v2(304.24,44.7) 302.49,44.7 300.2,46.99 294.57,46.99 292.1,49.45 292.1,62.63 291.97,62.77 291.75,62.77 291.62,62.9 291.62,63.09 291.75,63.22 291.97,63.22 292.1,63.36 292.1,64.99 v2(292.22,65.11)
I2C_PCA9548_SC3_SLOT2_R_SCL: length 4.6
  TOP w0.114: R26.1 299.67,41.68 v2(299.82,41.53) 300.05,41.3 301.25,41.3 301.54,41.01 U2.11
I2C_PCA9548_SC3_SLOT2_SCL: length 27
  TOP w0.114: v2(295.56,26.26) 295.56,26.43 295.55,26.43 295.55,26.65 295.23,26.98 R228.1 294.69,27.16 294.32,26.8 Q21.D ; R102.2 298.4,44.68 v2(298.4,44.32) 298.76,43.96 R26.2
  IN2 w0.147: v2(295.56,26.26) 295.56,26.87 297.52,28.83 297.52,41.47 297,41.99 297,43.26 298.07,44.32 v2(298.4,44.32)
I2C_PCA9548_SC4_SLOT1_R_SCL: length 5.8
  TOP w0.114: U2.14 301.54,33.72 299.8,31.98 299.8,30.58 v2(299.54,30.33) R339.1
I2C_PCA9548_SC4_SLOT1_SCL: length 12.9
  TOP w0.114: R339.2 299.54,28.52 v2(299.19,28.17) 299.54,27.81 R145.2 ; R307.1 296.6,23.11 Q20.D v2(299.88,22.1)
  IN2 w0.147: v2(299.19,28.17) 299.09,28.07 299.09,22.89 v2(299.88,22.1)
I2C_PCA9548_SC5_3V3_PE_SCL: length 177.4
  TOP w0.114: CON1.2 191.13,113.78 192.43,112.47 192.43,107.75 188.16,103.48 138.18,103.48 134.42,107.24 118.24,107.24 109.04,98.04 109.04,65 127.65,46.39 127.65,41.61 127.26,41.22 127.26,37.14 Q25.S 124.99,35.62 124.79,35.81 v2(124.79,36.58) 123.09,36.58 122.86,36.34 R194.2 R234.2 122.13,37.69 120.68,37.69 120.34,37.36 U12.7
I2C_PCA9548_SC5_P1V8_SCL: length 69.5
  TOP w0.114: v3(68.05,71.16) 68.47,70.75 70.86,70.75 71.38,70.23 71.38,69.95 71.88,69.44 73.53,69.44 74.07,69.98 93.28,69.98 v7(120.42,42.84) 120.34,42.76 U12.2
  BOTTOM w0.114: U1.F7 v3(68.05,71.16) ; R277.2 120.42,41.37 v7(120.42,42.84)
I2C_PCA9548_SC5_PE_R_SCL: length 3.6
  TOP w0.114: R28.1 301.83,32.77 v2(302.08,33.02) 302.84,33.78 U2.16
I2C_PCA9548_SC5_PE_SCL: length 199.1
  TOP w0.114: R234.1 122.99,38.12 v2(123.52,37.59) 124.56,37.59 Q25.D ; R28.2 301.83,30.56 v2(301.17,29.89) R104.2
  IN2 w0.147: v2(280.39,24.1) 280.39,23.11 279.25,21.97 267.93,21.97 266.57,23.32 257.74,23.32 254.74,26.31 180.69,26.31 162.94,44.07 130.35,44.07 123.88,37.59 v2(123.52,37.59)
  BOTTOM w0.114: v2(301.17,29.89) 300.1,28.83 296.95,28.83 295.78,27.66 294.41,27.66 290.37,23.62 287.17,23.62 285.64,25.15 283.4,25.15 282.65,24.41 280.7,24.41 v2(280.39,24.1)
I2C_PCA9548_SC6_3V3_CLK_R_SCL: length 7.7
  TOP w0.114: 302.11,56.32 U9.9 302.11,55.8 302.47,55.45 302.63,55.45 303.9,54.17 303.9,52.24 304.25,51.89 305.26,51.89 v2(305.52,51.64) R90.2
I2C_PCA9548_SC6_3V3_CLK_SCL: length 38.2
  TOP w0.114: R193.2 315.25,30.57 v2(315.47,30.36) 315.47,29.87 314.94,29.34 R236.2 314.55,28.66 314.34,28.45 Q19.S ; R90.1 v7(315.19,49.97)
  BOTTOM w0.114: v7(315.19,49.97) 316.02,49.97 318.85,47.14 318.85,33.67 317.28,32.1 317.28,31.94 317.57,31.65 317.57,31.44 317.37,31.24 317.2,31.24 316.88,31.56 316.74,31.56 315.54,30.36 v2(315.47,30.36)
I2C_PCA9548_SC6_CLK_R_SCL: length 3.6
  TOP w0.114: R30.1 304.14,31.67 304.14,32.69 v2(303.71,33.12) 304.14,33.55 U2.18
I2C_PCA9548_SC6_CLK_SCL: length 230
  TOP w0.114: v2(313.66,77.47) 313.91,77.72 316.69,77.72 317.7,78.74 317.7,86.77 310.62,93.85 211.11,93.85 195.97,78.71 189.03,78.71 R183.1 ; R30.2 303.86,30.15 v2(303.66,29.95) 303.86,29.74 R106.2 ; R280.2 v2(312.62,32.08) 313.08,31.62 313.08,30 R236.1 313.75,28.56 313.51,28.32 313.51,26.54 314.74,25.32 Q19.D
  BOTTOM w0.114: R299.1 v2(313.66,77.47) 313.66,76.09 311.85,74.28 306.14,74.28 304.05,72.2 304.05,65.46 312.73,56.78 312.73,48.18 313.16,47.75 313.16,41.78 312.09,40.72 312.09,33.53 312.62,32.99 v2(312.62,32.08) 312.47,32.08 311.79,31.39 309.15,31.39 308.81,31.06 304.6,31.06 303.66,30.12 v2(303.66,29.95)
I2C_PCA9548_SC6_FRU_SCL: length 2.2
  TOP w0.114: U7.6 R280.1
I2C_PCA9548_SC6_SEN1_SCL: length 3.9
  TOP w0.114: U10.10 185.03,79.5 v2(185.04,79.49) 187.45,79.49 R183.2
I2C_PCA9548_SC6_SEN2_SCL: length 3.7
  BOTTOM w0.114: U4.8 310.88,77.76 311.43,77.22 v4(311.61,77.22) 311.84,77.22 R299.2
I2C_PCA9548_SC7_ADC128_R_SCL: length 3.4
  TOP w0.114: U2.20 v2(305.44,33.25) 305.64,33.05 305.64,31.67 R142.1
I2C_PCA9548_SC7_ADC128_SCL: length 47.8
  TOP w0.114: R157.2 v2(267.18,29.08) ; R186.2 305.94,29.69 v2(306.2,29.95) 305.94,30.2 R142.2
  BOTTOM w0.114: v2(267.18,29.08) 267.18,28.68 267.62,28.24 270.02,28.24 274.9,23.37 281.89,23.37 282.65,22.61 290.83,22.61 293.65,25.43 297.87,25.43 299.04,26.59 303.94,26.59 305.61,28.27 305.61,28.63 306.2,29.21 v2(306.2,29.95)
I2C_PCA9548_SC7_ADC128_SCL_R: length 1.9
  TOP w0.114: U3.10 R157.1
I2C_PCA9548_SD1_SLOT3_R_SDA: length 4.4
  TOP w0.114: U2.6 304.79,42.11 304.5,42.41 v2(304.5,43.43) 305.11,43.43 R21.1
I2C_PCA9548_SD1_SLOT3_SDA: length 40.6
  TOP w0.114: R21.2 v2(305.39,44.73) R97.2 ; R227.1 287.97,68.43 288.16,68.24 Q18.D 288.16,66.3 v2(288.7,65.76)
  BOTTOM w0.114: v2(305.39,44.73) 304.65,45.47 302.41,45.47 300.41,47.47 294.77,47.47 292.58,49.65 292.58,64.06 292.99,64.47 292.99,65.48 292.48,65.99 288.93,65.99 v2(288.7,65.76)
I2C_PCA9548_SD3_SLOT2_R_SDA: length 3.6
  TOP w0.114: R25.1 v2(300.81,42.34) 302.19,40.97 U2.10
I2C_PCA9548_SD3_SLOT2_SDA: length 36.6
  TOP w0.114: Q24.D 288.57,26.8 v2(289,26.37) 289.13,26.49 R233.1 ; R25.2 300.77,43.96 v2(300.08,44.65) 300.81,45.39 R101.2
  IN2 w0.147: v2(289,26.37) 289,25.88 289.49,25.4 296.45,25.4 297.35,26.31 297.35,28.18 297.87,28.69 297.87,41.73 297.35,42.24 297.35,43.07 297.84,43.56 298.99,43.56 v2(300.08,44.65)
I2C_PCA9548_SD4_SLOT1_R_SDA: length 5.9
  TOP w0.114: R338.1 298.53,31.39 v2(298.91,31.77) 300.89,33.75 U2.13
I2C_PCA9548_SD4_SLOT1_SDA: length 16.6
  TOP w0.114: R144.2 298.43,27.45 v2(297.92,27.97) 298.53,28.57 R338.2 ; v2(293.79,22.1) Q23.D 290.51,23.11 R308.1
  IN2 w0.147: v2(293.79,22.1) 296.8,22.1 298.53,23.83 298.53,27.36 v2(297.92,27.97)
I2C_PCA9548_SD5_3V3_PE_SDA: length 177
  TOP w0.114: CON1.3 191.48,111.78 191.9,111.35 191.9,107.97 187.94,104.01 170.94,104.01 170.76,104.2 170.76,104.8 170.58,104.98 170.32,104.98 170.14,104.8 170.14,104.2 169.95,104.01 169.7,104.01 169.51,104.2 169.51,104.8 169.33,104.98 169.07,104.98 168.89,104.8 168.89,104.2 168.71,104.01 168.45,104.01 168.27,104.2 168.27,104.8 168.09,104.98 167.83,104.98 167.65,104.8 167.65,104.2 167.46,104.01 138.4,104.01 134.64,107.77 117.76,107.77 108.51,98.53 108.51,64.92 127.26,46.18 127.26,41.97 126.33,41.05 124.51,41.05 124.16,41.4 124.16,41.7 Q26.S 123.52,41.7 v2(123.52,40.89) 123.5,40.87 R209.2 R235.2 120.74,38.14 120.31,38.14 119.69,37.52 U12.6
I2C_PCA9548_SD5_P1V8_SDA: length 68.6
  TOP w0.114: v3(68.05,67.96) 68.46,67.56 72.95,67.56 74.78,69.4 93.04,69.4 v2(119.39,43.04) 119.69,42.74 U12.3
  BOTTOM w0.114: U1.F2 67.66,67.57 v3(68.05,67.96) ; v2(119.39,43.04) 119.62,42.81 119.62,41.59 R278.2
I2C_PCA9548_SD5_PE_R_SDA: length 3.8
  TOP w0.114: R27.1 v2(300.69,32.08) 300.69,32.26 302.19,33.76 U2.15
I2C_PCA9548_SD5_PE_SDA: length 195.7
  TOP w0.114: Q26.D 124.09,39.12 v2(123.65,39.12) 123.63,39.1 R235.1 ; R103.2 300.69,29.62 v2(300.36,29.95) 300.69,30.28 R27.2
  IN2 w0.147: v2(123.65,39.12) 124.64,39.12 130.25,44.73 163.21,44.73 180.97,26.97 255.01,26.97 258.19,23.8 267.03,23.8 268.51,22.32 276.9,22.32 v2(279.48,24.89)
  BOTTOM w0.114: v2(300.36,29.95) 299.75,29.34 295.33,29.34 291.51,25.52 283.1,25.52 282.48,24.89 v2(279.48,24.89)
I2C_PCA9548_SD6_3V3_CLK_R_SDA: length 6.8
  TOP w0.114: R89.2 v2(303.87,51.39) 303.53,51.73 303.53,54.02 302.49,55.06 302.35,55.06 301.71,55.69 U9.8 301.71,56.32
I2C_PCA9548_SD6_3V3_CLK_SDA: length 41.4
  TOP w0.114: R89.1 304.52,49.97 305.26,49.23 v2(314.48,49.23) ; Q22.S 310.15,28.45 310.07,28.53 R237.2 310.07,29.52 310.52,29.97 310.67,29.97 v2(310.9,30.2) 311.35,30.66 R204.2
  BOTTOM w0.114: v2(310.9,30.2) 313.02,30.2 314.14,31.32 315.88,31.32 318.47,33.91 318.47,46.69 315.93,49.23 v2(314.48,49.23)
I2C_PCA9548_SD6_CLK_R_SDA: length 3.4
  TOP w0.114: U2.17 303.49,33.72 302.95,33.17 v2(302.95,32.03) 302.85,31.93 R29.1
I2C_PCA9548_SD6_CLK_SDA: length 232.7
  TOP w0.114: R105.2 v2(302.85,29.95) R29.2 ; R279.2 311.94,32.29 311.94,30.89 v2(312.09,30.73) 312.09,30.56 R237.1 310.87,28.56 311.1,28.32 Q22.D ; R184.1 197.12,78.25 212.22,93.34 310.49,93.34 317.2,86.64 317.2,78.87 316.43,78.11 314.66,78.11 314.53,78.23 v2(314.53,78.61)
  BOTTOM w0.114: v2(302.85,29.95) 302.85,29.62 303.07,29.39 304.04,29.39 304.32,29.67 304.32,30.18 304.75,30.61 309.37,30.61 309.73,30.96 311.86,30.96 v2(312.09,30.73) 312.8,30.73 313.56,31.5 313.56,33.27 312.62,34.21 312.62,40.23 314.5,42.11 314.5,47.29 313.09,48.7 313.09,56.93 304.42,65.61 304.42,72.01 306.33,73.91 312.37,73.91 314.53,76.07 v2(314.53,78.61) 314.02,79.12 R300.1
I2C_PCA9548_SD6_FRU_SDA: length 2.2
  TOP w0.114: U7.5 R279.1
I2C_PCA9548_SD6_SEN1_SDA: length 4.2
  TOP w0.114: U10.9 184.71,79 184.95,78.77 v2(186.46,78.77) 186.98,78.25 R184.2
I2C_PCA9548_SD6_SEN2_SDA: length 3.4
  BOTTOM w0.114: R300.2 312.09,79.12 v4(311.6,78.63) 311.39,78.41 U4.7
I2C_PCA9548_SD7_ADC128_R_SDA: length 3.2
  TOP w0.114: R141.1 304.79,31.5 v2(304.79,32.15) U2.19
I2C_PCA9548_SD7_ADC128_SDA: length 47.1
  TOP w0.114: R158.2 267.57,27.94 267.69,28.07 267.69,28.83 v2(267.92,29.06) ; R185.2 v2(304.93,29.95) R141.2
  BOTTOM w0.114: v2(304.93,29.95) 304.93,28.12 303.96,27.15 294.49,27.15 290.45,23.11 282.65,23.11 282.12,23.65 275.64,23.65 270.64,28.65 268.17,28.65 267.92,28.91 v2(267.92,29.06)
I2C_PCA9548_SD7_ADC128_SDA_R: length 2.2
  TOP w0.114: U3.9 265.24,28.45 R158.1
I2C_PE_SCL: length 35
  TOP w0.114: v2(308.76,26.19) 307.98,26.97 R86.1
  IN1 w0.147: v2(308.76,26.19) 308,26.19 303.1,21.29 303.1,15.43 297.52,9.86 293.98,9.86 292.76,8.64 292.76,8.48 292.3,8.03 v2(292.3,7.87)
  BOTTOM w0.114: J5.B5 291.83,5.94 291.54,6.22 291.54,7.11 v2(292.3,7.87)
I2C_PE_SCL_R: length 5.8
  TOP w0.114: R86.2 R87.2 307.47,31.07 307.47,32.74 v2(306.96,33.25) 306.74,33.47 U2.22
I2C_PE_SDA: length 34.5
  TOP w0.114: R85.1 v2(308.99,27.69)
  IN1 w0.147: v2(292.24,8.7) 293.76,10.21 297.31,10.21 302.74,15.65 302.74,21.51 308.92,27.69 v2(308.99,27.69)
  BOTTOM w0.114: J5.B6 290.83,7.28 v2(292.24,8.7)
I2C_PE_SDA_R: length 6
  TOP w0.114: U2.23 307.39,33.58 v2(308.36,32.61) 308.48,32.49 308.48,31.07 R88.2 R85.2
I2C_SC5_2N7002_G_SCL: length 3.2
  TOP w0.114: Q25.G v1(123.84,33.94) 123.12,33.94 R161.2
I2C_SC6_2N7002_G_SCL: length 2.1
  TOP w0.254: R160.2 v2(315.7,28.7) 316.24,28.16 Q19.G
I2C_SD5_2N7002_G_SDA: length 3.1
  TOP w0.114: R191.2 125.54,43.66 v1(126.52,43.66) 126.52,42.8 Q26.G
I2C_SD6_2N7002_G_SDA: length 1.9
  TOP w0.254: R163.2 v2(311.84,28.7) 312.05,28.49 Q22.G
I2C_SLOT1_2N7002_G_SCL: length 2.2
  TOP w0.114: Q20.G 297.23,24.51 v2(296.5,24.51) 296.26,24.28 R301.2
I2C_SLOT1_2N7002_G_SDA: length 2.2
  TOP w0.114: R342.2 290.17,24.28 v2(290.4,24.51) 291.14,24.51 Q23.G
I2C_SLOT1_3V3_SCL: length 9.5
  TOP w0.114: J1.B5 291.83,20.35 292.05,20.57 293.85,20.57 R303.2 R307.2 296.88,21.95 297.09,22.16 Q20.S
I2C_SLOT1_3V3_SDA: length 5.8
  TOP w0.114: Q23.S 290.87,22.16 290.65,21.95 R308.2 R304.2 289.13,21.77 290.83,20.07 J1.B6
I2C_SLOT2_2N7002_G_SCL: length 2.7
  TOP w0.254: R162.2 v2(294.45,24.52) 293.79,25.19 Q21.G
I2C_SLOT2_2N7002_G_SDA: length 2.7
  TOP w0.254: R192.2 288.86,25.02 288.37,25.02 288.11,24.77 v2(287.69,24.77) Q24.G
I2C_SLOT2_3V3_SCL: length 32.6
  TOP w0.114: v2(295.86,28.57) 296.24,28.19 R203.2 R228.2 294.93,27.96 294.72,27.75 Q21.S
  IN2 w0.147: v2(295.86,28.57) 296.41,29.12 296.41,29.93 296.24,30.1 293.21,30.1 293.07,30.25 293.07,30.67 293.21,30.82 296.46,30.82 296.6,30.97 296.6,31.2 296.46,31.35 294.99,31.35 294.84,31.5 294.84,31.86 294.99,32 296.66,32 296.81,32.15 296.81,39.63 295.64,40.8 292.46,40.8 291.83,40.16 J2.B5
I2C_SLOT2_3V3_SDA: length 29.7
  TOP w0.114: v2(290.15,28.68) R210.2 R233.2 288.62,27.96 288.41,27.75 Q24.S
  IN2 w0.147: v2(290.15,28.68) 290.4,28.68 291.21,27.86 295.96,27.86 297.16,29.06 297.16,39.78 295.78,41.15 291.54,41.15 290.83,40.43 J2.B6
I2C_SLOT3_2N7002_G_SCL: length 2.2
  TOP w0.254: R107.2 295.96,66.21 v2(295.61,65.85) Q15.G
I2C_SLOT3_2N7002_G_SDA: length 2.3
  TOP w0.254: Q18.G 289.76,65.26 v2(289.76,64.77) 289.54,64.54 R153.2
I2C_SLOT3_3V3_SCL: length 13.8
  TOP w0.114: R226.2 293.24,69.09 v2(293.27,69.06) 293.3,69.09 R156.2 294.42,68.6 Q15.S
  BOTTOM w0.114: v2(293.27,69.06) 292.76,69.06 292.03,69.8 292.03,74.35 291.05,75.32 291.05,77.61 J3.B5
I2C_SLOT3_3V3_SDA: length 14.7
  TOP w0.114: Q18.S 290.36,68.37 290.13,68.6 R159.2 v2(289.41,69.09) R227.2
  BOTTOM w0.114: v2(289.41,69.09) 289.97,69.65 289.97,74.6 290.61,75.24 290.61,80.18 J3.B6
JTAG_R_TCK: length 4.4
  TOP w0.114: R306.1 293.45,11.95 293.7,12.19 293.7,13.21 292.69,14.22 292.54,14.22 J1.A5
JTAG_R_TDI: length 1.8
  TOP w0.114: J1.A6 291.67,12.09 R347.1
JTAG_R_TDO: length 3.8
  TOP w0.114: J1.A7 289.83,12.76 289,11.94 R354.1
JTAG_R_TMS: length 1.8
  TOP w0.114: R355.1 288.11,12.22 J1.A8
JTAG_TCK: length 8.5
  TOP w0.114: R306.2 R358.2 291.65,9.74 291.65,6.11 291.83,5.94 J5.A5
JTAG_TDI: length 8.4
  TOP w0.114: R347.2 R359.2 290.78,10.41 291.27,9.93 291.27,6.2 290.83,5.76 J5.A6
JTAG_TDO: length 8.9
  TOP w0.114: R354.2 R357.2 290.89,9.65 290.89,6.66 289.83,5.6 J5.A7
JTAG_TMS: length 9.3
  TOP w0.114: J5.A8 288.83,5.95 289.64,6.76 289.64,9.65 289.13,10.16 288.6,10.16 R355.2 R356.2
JTAG_TRST_N: length 21.9
  TOP w0.114: R360.2 284.94,21.4 286.01,20.33 287.22,20.33 287.8,19.76 287.8,19.75 287.83,19.72 J1.B9
  BOTTOM w0.114: J5.B9 287.83,9.14 285.91,11.06 285.91,13.65 286.84,14.58 286.84,16.45 J1.B9
NC_JTAG_TCK: length 0.6
  BOTTOM w0.114: U1.G11 v3(67.25,74.36)
NC_JTAG_TDI: length 0.6
  BOTTOM w0.114: U1.J6 v3(65.65,70.36)
NC_JTAG_TDO: length 0.6
  BOTTOM w0.114: U1.F11 v3(68.05,74.36)
NC_JTAG_TMS: length 0.6
  BOTTOM w0.114: U1.H11 v3(66.45,74.36)
NC_PEX_FATAL_ERR_N: length 0.6
  BOTTOM w0.114: U1.F14 v3(68.05,77.57)
NC_PEX_INTA_N: length 0.6
  BOTTOM w0.114: U1.B6 v3(70.45,70.36)
PCA9617_EN: length 3.8
  TOP w0.114: U12.5 118.97,37.71 v2(119.1,37.85)
  BOTTOM w0.114: v2(119.1,37.85) 119.08,37.82 R276.1 R296.2
PCIE_SLOT1_WAKE_N: length 5.7
  TOP w0.114: J1.B11 285.83,18.21 282.91,21.13 R370.2
PCIE_SLOT2_WAKE_N: length 4.9
  TOP w0.114: J2.B11 R8.2
PCIE_SLOT3_WAKE_N: length 4.8
  TOP w0.114: J3.B11 R7.2
PCIE_SLOT_PRES_N: length 117.6
  TOP w0.114: v2(278.84,21.16) 278.48,21.52 R9.2 R165.1 ; v2(265.41,21.97) R34.2 264.64,22.28 264.26,22.66 261.77,22.66 260.73,23.7 258.01,23.7 256.29,21.97 R77.2 246.12,23.6 240.41,23.6 238.79,21.97 R5.2 ; J5.A1 295.83,5.8 295.12,6.5 295.12,8.43 296.48,9.79 298.29,9.79 298.65,10.16 298.65,12.57 v2(298.15,13.08)
  IN1 w0.147: v2(278.84,21.16) 278.84,21.13 279.45,20.52 281.33,20.52 281.81,20.04 281.81,18.64 280.87,17.7 280.87,15.34 280.76,14.69 279.94,13.51 279.94,11.89 280.49,11.33 282.32,11.33 283.62,10.03 293.07,10.03 293.65,10.62 297.21,10.62 298.15,11.56 v2(298.15,13.08)
  IN2 w0.147: J1.A1 297.68,13.08 v2(298.15,13.08) ; v2(265.41,21.97) 265.76,21.62 278.39,21.62 v2(278.84,21.16)
PCIE_X1_SLOT1_PRES_N: length 7.9
  TOP w0.114: J1.B17 277.83,19.94 275.9,21.86 R166.2 275.9,22.59 276.3,22.99 R165.2
PCIE_X1_SLOT_PRES_N: length 21
  TOP w0.114: R166.1 R9.1 v2(277.68,21.08)
  BOTTOM w0.114: J5.B17 277.83,5.72 276.81,6.73 276.81,7.95 277.83,8.97 277.83,13.34 276.86,14.3 276.86,17.93 277.73,18.8 277.73,21.03 v2(277.68,21.08)
PCIE_X4_SLOT_PRES_N: length 19.6
  TOP w0.114: J1.B31 263.84,17.44 R34.1
  BOTTOM w0.114: J1.B31 262.71,16.32 262.71,14.5 263.7,13.51 263.7,12.29 263.43,12.01 263.43,6.27 263.83,5.87 J5.B31
PCIE_X8_SLOT_PRES_N: length 19.3
  TOP w0.114: J1.B48 246.82,19.44 246.82,21.84 R77.1
  BOTTOM w0.114: J1.B48 246.83,14.59 245.82,13.59 245.82,6.61 246.83,5.61 J5.B48
PCIE_X16_SLOT_PRES_N: length 19.4
  TOP w0.114: J1.B81 213.83,21.49 R5.1
  BOTTOM w0.114: J1.B81 212.88,16.49 212.88,14.25 213.69,13.44 v2(213.69,8.71) 213.13,8.15 213.13,6.5 213.83,5.81 J5.B81
PD_FRU_WP: length 4.4
  TOP w0.114: 313.89,35.84 313.89,35.18 314.45,34.62 314.45,33.43 R294.1 R293.2
PD_JTAG_TRST_N: length 4
  TOP w0.102: v3(67.25,67.96) 67.41,67.96 67.82,68.38 70.09,68.38 R10.1
  BOTTOM w0.114: U1.F3 67.65,68.36 v3(67.25,67.96)
PD_REXT_A0: length 45.7
  TOP w0.114: R11.1 v2(32.21,106.43)
  IN1 w0.102: 50.61,77.17 50.64,77.17 51.76,76.05 52.17,76.05 52.47,75.75 55.72,75.75 56.31,75.17 v3(56.85,75.17)
  IN1 w0.147: v2(32.21,106.43) 32.21,104.31 32.82,103.7 32.82,103.31 32.76,103.25 32.76,98.9 35.56,96.1 35.56,92.22 50.61,77.17
  BOTTOM w0.114: U1.W11 57.25,74.77 v3(56.85,75.17)
PD_REXT_A1: length 48.6
  TOP w0.114: R12.1 29.67,107.84 29.67,107.06 v2(30.3,106.43)
  IN1 w0.102: 47.66,78.85 49.51,77 49.51,75.97 50.69,74.78 55.63,74.78 v3(56.05,74.36)
  IN1 w0.147: v2(30.3,106.43) 30.35,106.38 30.35,99.95 34,96.3 34,92.5 47.66,78.85
  BOTTOM w0.114: U1.Y11 v3(56.05,74.36)
PD_REXT_A2: length 20.9
  TOP w0.114: R13.1 54.18,94.13 54.18,91.06 v2(53.04,89.92)
  IN1 w0.102: v3(56.05,77.57) 56.05,77.68 55.78,77.95 54.21,77.95 52.76,79.4 52.76,89.64 v2(53.04,89.92)
  BOTTOM w0.114: U1.Y14 v3(56.05,77.57)
PD_REXT_A3: length 19.4
  TOP w0.114: R14.1 55.32,94.13 55.32,90.68 54.81,90.17 v2(54.81,89.92)
  IN1 w0.102: v3(56.85,79.17) 56.47,79.55 54.26,79.55 54.03,79.77 54.03,87.87 54.81,88.65 v2(54.81,89.92)
  BOTTOM w0.114: v3(56.85,79.17) 57.25,78.77 U1.W16
PD_REXT_A4: length 3.7
  TOP w0.114: v5(62.01,65.35) 61.92,65.45 R15.1
  BOTTOM w0.114: v5(62.01,65.35) 61.6,65.77 61.6,66.41 61.67,66.49 61.67,67.24 62,67.57 U1.N2
PD_REXT_A5: length 6.7
  TOP w0.102: R16.1 71.05,68.99 v4(70.44,69.6) 70.05,69.98 67.77,69.98 67.64,70.1 67.64,70.74 67.25,71.13 v3(67.25,71.16)
  BOTTOM w0.114: U1.G7 v3(67.25,71.16)
PD_REXT_A6: length 5.8
  TOP w0.102: R17.1 72.07,70.22 v4(70.41,71.88) 70.09,71.57 68.45,71.57 v3(68.05,71.96)
  BOTTOM w0.114: v3(68.05,71.96) 67.65,72.36 U1.F8
PD_REXT_A7: length 5.2
  TOP w0.102: v3(68.05,73.56) 68.44,73.95 70.09,73.95 v4(70.56,74.42)
  TOP w0.114: R18.1 71.26,73.72 v4(70.56,74.42)
  BOTTOM w0.114: U1.F10 v3(68.05,73.56)
PD_REXT_A8: length 1.7
  TOP w0.102: R19.1 60.02,83.93 v3(59.25,83.17)
  BOTTOM w0.114: U1.T21 59.65,82.77 v3(59.25,83.17)
PD_REXT_A9: length 1.5
  TOP w0.114: v3(64.05,83.97) 64.29,84.2 R20.1
  BOTTOM w0.114: U1.K22 64.45,83.57 v3(64.05,83.97)
PD_REXT_A10: length 7
  TOP w0.109: 71.75,79.5 71.43,79.18 71.43,78.21 70.82,77.6 v4(70.46,77.6) 70.08,77.98 67.67,77.98 v3(67.25,77.57)
  TOP w0.114: 71.75,79.5 71.94,79.69 R23.1
  BOTTOM w0.114: U1.G14 v3(67.25,77.57)
PD_REXT_A11: length 7.6
  TOP w0.102: v3(67.25,76.77) 67.25,76.56 67.54,76.28 71.15,76.28 71.45,76.58 v4(71.57,76.58)
  TOP w0.109: v4(71.57,76.58) 71.78,76.8 71.78,78.52
  TOP w0.114: R24.1 71.94,78.68 71.78,78.52
  BOTTOM w0.114: U1.G13 v3(67.25,76.77)
PD_REXT_B0: length 46.4
  TOP w0.114: v2(29.54,104.39) 29.16,104.78 R31.1
  IN1 w0.102: 50.09,74.66 50.23,74.51 52.75,74.51 53.3,73.96 55.65,73.96 v3(56.05,73.56)
  IN1 w0.147: 50.09,74.66 48.95,75.79 48.95,77.13 33.5,92.58 33.5,96.24 29.68,100.07 29.68,104.26 v2(29.54,104.39)
  BOTTOM w0.114: U1.Y10 56.45,73.96 v3(56.05,73.56)
PD_REXT_B1: length 52
  TOP w0.114: v2(28.53,105.79) 28.53,107.72 R32.1
  IN1 w0.102: v3(56.85,73.56) 56.47,73.18 53.8,73.18 53.01,73.96 50.34,73.96 50.2,74.11
  IN1 w0.147: 50.2,74.11 48.41,75.9 48.41,77.24 33.2,92.45 33.2,96.11 29.38,99.94 29.38,103.46 28.53,104.31 v2(28.53,105.79)
  BOTTOM w0.114: v3(56.85,73.56) 57.65,73.56 U1.V10
PD_REXT_B2: length 41.5
  TOP w0.114: v2(34.24,104.52) R33.1
  IN1 w0.102: 48.97,80.1 52.36,76.72 52.72,76.72 53.06,76.38 55.86,76.38 56.05,76.57 v3(56.05,76.77)
  IN1 w0.147: 48.97,80.1 37.05,92.03 37.05,102.77 35.3,104.52 v2(34.24,104.52)
  BOTTOM w0.114: U1.Y13 v3(56.05,76.77)
PD_REXT_B3: length 18.6
  TOP w0.114: v2(53.93,88.9) 53.93,90.04 54.81,90.93 R132.1
  IN1 w0.102: v2(53.93,88.9) 53.16,88.14 53.16,79.38 53.75,78.78 56.21,78.78 56.43,78.56 56.43,77.98 v3(56.85,77.57)
  BOTTOM w0.114: U1.W15 v3(56.85,77.57)
PD_REXT_B4: length 55.9
  TOP w0.114: R35.1 v2(26.87,106.93)
  IN1 w0.102: 47.66,75.53 49.91,73.28 52.58,73.28 53.49,72.36 56.29,72.36 56.47,72.19 56.47,71.65 56.85,71.27 v3(56.85,71.16)
  IN1 w0.147: v2(26.87,106.93) 27.23,106.58 27.23,104.47 28.78,102.92 28.78,99.69 32.61,95.87 32.61,91.75 33.68,90.68 33.68,85.45 34.77,84.35 40.46,84.35 47.35,77.46 47.35,75.84 47.66,75.53
  BOTTOM w0.114: v3(56.85,71.16) 57.25,71.56 U1.W7
PD_REXT_B5: length 5.1
  TOP w0.102: v3(64.05,70.36) 63.93,70.36 63.65,70.09 63.65,68.4 v4(63.93,68.12) 63.66,67.85 63.66,67.09 R36.1
  BOTTOM w0.114: U1.L6 v3(64.05,70.36)
PD_REXT_B6: length 6
  TOP w0.102: R37.1 71.69,71.37 70.68,72.38 67.64,72.38 67.25,72 v3(67.25,71.96)
  BOTTOM w0.114: U1.G8 66.85,72.36 v3(67.25,71.96)
PD_REXT_B7: length 6.1
  TOP w0.109: v3(67.25,73.56) 67.67,73.15 67.89,73.15 67.9,73.15 69.27,73.15 v4(69.5,72.92) 69.72,73.15 71.25,73.15 R38.1
  BOTTOM w0.114: U1.G10 66.85,73.96 v3(67.25,73.56)
PD_REXT_B8: length 1.4
  TOP w0.102: v3(59.25,83.97) 58.43,83.97 R133.1
  BOTTOM w0.114: U1.T22 59.65,83.57 v3(59.25,83.97)
PD_REXT_B9: length 10.8
  TOP w0.102: v3(68.05,79.97) 68.05,80 68.41,80.35 69.9,80.35 70.06,80.51 70.06,84.35 70.54,84.84 v4(71.63,84.84)
  TOP w0.114: v4(71.63,84.84) 71.94,84.52 R134.1
  BOTTOM w0.114: v3(68.05,79.97) 67.25,79.97 U1.G17
PD_REXT_B10: length 6.9
  TOP w0.102: v3(67.25,78.37) 67.46,78.37 67.85,78.76 69.88,78.76 70.06,78.93 70.06,79.77 70.19,79.91 v4(70.64,79.91)
  TOP w0.114: v4(70.64,79.91) 70.78,79.91 71.94,81.07 R41.1
  BOTTOM w0.114: v3(67.25,78.37) 66.86,78.76 U1.G16
PD_REXT_B11: length 7.9
  TOP w0.109: v5(72.59,75.98) 72.85,75.98 72.93,75.89 73.73,75.89 R42.1
  BOTTOM w0.114: U1.H13 66.07,76.37 66.45,75.98 v5(72.59,75.98)
PD_REXT_CMU: length 47.9
  TOP w0.114: v2(31.57,104.9) 31.19,105.28 R43.1
  IN1 w0.102: v3(56.85,74.37) 56.6,74.37 55.42,75.55 52.68,75.55 52.12,74.99 50.97,74.99 49.96,76 49.96,76.97 47.66,79.27
  IN1 w0.147: 47.66,79.27 34.9,92.03 34.9,95.83 31.73,99 31.73,104.75 v2(31.57,104.9)
  BOTTOM w0.114: U1.W10 v3(56.85,74.37)
PD_SLOT2_A1: length 12.8
  TOP w0.114: v2(289.64,42.67) 288.9,42.67 R200.1
  BOTTOM w0.114: J2.A1 295.83,35.59 294.97,36.45 291.42,36.45 290.91,36.96 290.91,37.97 289.64,39.24 v2(289.64,42.67)
PD_SLOT3_A1: length 11.9
  TOP w0.114: R199.1 v2(289.62,83.17)
  BOTTOM w0.114: v2(289.62,83.17) 289.66,83.17 291.16,81.66 293.32,81.66 294.05,80.93 294.05,79.54 294.84,78.74 294.84,76.88 J3.A1
PD_VOE_N: length 18.1
  TOP w0.114: v7(305.59,62.84) 305.21,62.47 R76.2 ; v2(304.2,60.45) 303.84,60.1 U9.19 303.09,60.1 ; 303.09,57.7 U9.13 304.1,57.7 v2(304.2,57.61) ; v2(302.11,62.05) 302.11,62.05 U9.22 302.11,61.07 ; v2(299.54,62.04) 299.71,61.87 U9.28 299.71,61.07
  IN1 w0.147: v2(304.2,57.61) v2(304.2,60.45) 304.2,61.45 v7(305.59,62.84) 305.24,63.19 303.25,63.19 v2(302.11,62.05) 302.1,62.04 v2(299.54,62.04)
PE_CPU_RX_DN<0>: length 12.1
  TOP w0.135: J5.A17 277.83,5.8 278.17,6.15 278.17,7.45 v2(277.83,7.8)
  IN2 w0.145: v2(277.83,7.8) 278.2,8.17 278.2,9.13 277.61,12.46 277.86,13.88 278.11,14.09 278.15,14.29 J1.A17
PE_CPU_RX_DN<1>: length 12.1
  TOP w0.135: v2(272.82,7.8) 273.17,7.45 273.17,6.15 272.83,5.8 J5.A22
  IN2 w0.145: J1.A22 273.22,13.72 273.41,13.78 273.42,13.78 273.52,13.71 273.55,13.69 273.69,12.9 273.85,11.99 273.76,11.47 273.63,11.38 273.53,10.81 273.62,10.69 273.54,10.25 273.42,10.16 273.31,9.59 273.4,9.47 273.17,8.15 v2(272.82,7.8)
PE_CPU_RX_DN<2>: length 12.1
  TOP w0.135: v2(268.84,7.8) 269.17,7.46 269.17,6.15 268.83,5.8 J5.A26
  IN2 w0.145: v2(268.84,7.8) 269.15,8.02 269.4,9.47 269.31,9.59 269.42,10.16 269.54,10.25 269.62,10.69 269.53,10.81 269.63,11.38 269.76,11.47 269.85,11.99 269.69,12.9 269.55,13.69 269.52,13.71 269.42,13.78 269.41,13.78 269.22,13.72 J1.A26
PE_CPU_RX_DN<3>: length 12.1
  TOP w0.135: v2(264.82,7.8) 265.17,7.45 265.17,6.18 264.83,5.83 J5.A30
  IN2 w0.145: J1.A30 265.22,13.72 265.41,13.78 265.42,13.78 265.52,13.71 265.55,13.69 265.69,12.9 265.85,11.99 265.76,11.47 265.63,11.38 265.53,10.81 265.62,10.69 265.54,10.25 265.42,10.16 265.31,9.59 265.4,9.47 265.15,8.03 v2(264.82,7.8)
PE_CPU_RX_DN<4>: length 12.1
  TOP w0.135: J5.A36 258.83,5.8 259.17,6.15 259.17,7.46 v2(258.83,7.8)
  IN2 w0.145: J1.A36 259.22,13.72 259.41,13.78 259.42,13.78 259.52,13.71 259.55,13.69 259.69,12.9 259.85,11.99 259.76,11.47 259.63,11.38 259.53,10.81 259.62,10.69 259.54,10.25 259.42,10.16 259.31,9.59 259.4,9.47 259.15,8.03 v2(258.83,7.8)
PE_CPU_RX_DN<5>: length 12.1
  TOP w0.135: J5.A40 254.83,5.8 255.17,6.15 255.17,7.44 v2(254.81,7.8)
  IN2 w0.145: v2(254.81,7.8) 255.15,8.04 255.4,9.47 255.31,9.59 255.42,10.16 255.54,10.25 255.62,10.69 255.53,10.81 255.63,11.38 255.76,11.47 255.85,11.99 255.69,12.9 255.55,13.69 255.52,13.71 255.42,13.78 255.41,13.78 255.22,13.72 J1.A40
PE_CPU_RX_DN<6>: length 12.1
  TOP w0.135: v2(250.83,7.8) 251.17,7.45 251.17,6.15 250.83,5.8 J5.A44
  IN2 w0.145: J1.A44 251.22,13.72 251.41,13.78 251.42,13.78 251.52,13.71 251.55,13.69 251.69,12.9 251.85,11.99 251.76,11.47 251.63,11.38 251.53,10.81 251.62,10.69 251.54,10.25 251.42,10.16 251.31,9.59 251.4,9.47 251.15,8.03 v2(250.83,7.8)
PE_CPU_RX_DN<7>: length 12.1
  TOP w0.135: v2(246.81,7.8) 247.17,7.44 247.17,6.15 246.83,5.8 J5.A48
  IN2 w0.145: J1.A48 247.22,13.72 247.41,13.78 247.42,13.78 247.52,13.71 247.55,13.69 247.69,12.9 247.85,11.99 247.76,11.47 247.63,11.38 247.53,10.81 247.62,10.69 247.54,10.25 247.42,10.16 247.31,9.59 247.4,9.47 247.15,8.04 v2(246.81,7.8)
PE_CPU_RX_DN<8>: length 12.1
  TOP w0.135: v2(241.84,7.8) 242.17,7.46 242.17,6.15 241.83,5.8 J5.A53
  IN2 w0.145: v2(241.84,7.8) 242.2,8.16 242.2,9.13 241.61,12.46 241.86,13.88 242.11,14.09 242.15,14.29 J1.A53
PE_CPU_RX_DN<9>: length 12.1
  TOP w0.135: v2(237.82,7.8) 238.17,7.45 238.17,6.15 237.83,5.8 J5.A57
  IN2 w0.145: v2(237.82,7.8) 237.83,7.8 238.2,8.17 238.2,9.13 237.61,12.46 237.86,13.88 238.11,14.09 238.15,14.29 J1.A57
PE_CPU_RX_DN<10>: length 12.2
  TOP w0.135: v2(233.81,7.8) 234.17,7.44 234.17,6.15 233.83,5.8 J5.A61
  IN2 w0.145: v2(233.81,7.8) 233.83,7.8 234.2,8.17 234.2,9.13 233.61,12.46 233.86,13.88 234.11,14.09 234.18,14.44 J1.A61
PE_CPU_RX_DN<11>: length 12.2
  TOP w0.135: v2(229.82,7.8) 230.17,7.45 230.17,6.15 229.83,5.8 J5.A65
  IN2 w0.145: J1.A65 230.18,14.44 230.11,14.09 229.86,13.88 229.61,12.46 230.2,9.13 230.2,8.17 229.83,7.8 v2(229.82,7.8)
